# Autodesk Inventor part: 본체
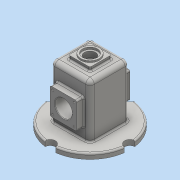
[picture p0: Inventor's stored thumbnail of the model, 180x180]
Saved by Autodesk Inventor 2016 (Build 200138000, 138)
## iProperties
Created: 2018-07
Part Number: 본체
Material: 일반
Document SubType Name: Modeling
Designer: 2-PC02
Density: 1 g/cm^3
Appearance: 기본값
Mass: 461.374 g
Surface Area: 953.172 cm^2
Volume: 461.374 cm^3
Author: 2-PC02
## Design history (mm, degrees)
sketch "스케치1"
  geometry: C1 r 75 at (0, 0); 1 further point
  constraints: 1 centre point, 1 coincident
  dimensions: "d0" = 150 diameter of C1
extrude "돌출1" new body sketch "스케치1" distance "d1" = 10; taper "d2" = 0 deg
sketch "스케치2"
  geometry: L1 (37, -37)-(-37, -37); L2 (-37, -37)-(-37, 37); L3 (-37, 37)-(37, 37); L4 (37, 37)-(37, -37); L5 (37, -37)-(-37, 37); L6 (-37, -37)-(37, 37); 1 further point
  constraints: 12 end point, 2 midpoint, 2 parallel, 1 horizontal, 1 perpendicular
  dimensions: "d3" = 74 distance of L2.end L3.end; "d4" = 74 distance of L1.end L2.end
extrude "돌출2" join sketch "스케치2" distance "d5" = 100; taper "d6" = 0 deg
sketch "스케치3"
  geometry: L1 (20, -20)-(-20, -20); L2 (-20, -20)-(-20, 20); L3 (-20, 20)-(20, 20); L4 (20, 20)-(20, -20); L5 (20, -20)-(-20, 20); L6 (-20, -20)-(20, 20); 1 further point
  constraints: 12 end point, 2 midpoint, 2 parallel, 1 horizontal, 1 perpendicular
  dimensions: "d7" = 40 distance of L2.end L3.end; "d8" = 40 distance of L3.end L1.start
extrude "돌출3" join sketch "스케치3" distance "d9" = 7; taper "d10" = 0 deg
sketch "스케치4"
  geometry: C1 r 17.5 at (0, 0); 1 further point
  constraints: 1 centre point, 1 coincident
  dimensions: "d11" = 35 diameter of C1
extrude "돌출4" join sketch "스케치4" distance "d12" = 3; taper "d13" = 0 deg
sketch "스케치5"
  geometry: L1 (62, 20)-(12, 20); L2 (12, 20)-(12, 70); L3 (12, 70)-(62, 70); L4 (62, 70)-(62, 20); L5 (62, 20)-(12, 70); L6 (12, 20)-(62, 70); L7 (-38, -10)-(112, -10) reference; 2 further points
  constraints: 12 end point, 2 midpoint, 2 parallel, 1 horizontal, 1 perpendicular
  dimensions: "d14" = 50 distance of L2.end L3.end; "d15" = 50 distance of L1.end L2.end; "d16" = 55 distance from line of L7 point (37, 45)
extrude "돌출5" join sketch "스케치5" distance "d17" = 13; taper "d18" = 0 deg
sketch "스케치7"
  geometry: 2 further points
  constraints: 1 coincident
hole "구멍1" sketch "스케치7" at (0, 0) diameter "d23" = 21; stored, may be unused: countersink angle "d27" = 90 deg, drill point angle "d29" = 0 deg; dims "d24" = 6, "d25" = 28, "d26" = 4, "d28" = 15
sketch "스케치12"
  geometry: L1 (-38, -10)-(112, -10) reference; 2 further points
  dimensions: "d54" = 55 distance from line of L1 point (37, 45)
hole "구멍2" sketch "스케치12" at (37, 45) diameter "d55" = 32; stored, may be unused: countersink angle "d59" = 110 deg, drill point angle "d61" = 0 deg; dims "d56" = 6, "d57" = 64, "d58" = 4, "d60" = 100
sketch "스케치13"
  geometry: L1 (10.5, 105)-(-10.5, 105) reference; L2 (-32, 105)-(-32, 80); L3 (-32, 80)-(-25, 77.452); L4 (-32, 105)-(0, 105); L5 (0, 0)-(0, 105); L6 (-37, 10)-(-37, 110) reference; L7 (-50, 39)-(-50, 71) reference; L8 (-25, 77.452)-(0, 77.452)
  constraints: 10 end point, 2 perpendicular, 1 midpoint, 1 point on line
  dimensions: "d62" = 5 distance between parallel lines of L6 L2
revolve "회전3" sketch "스케치13" stored, may be unused: angle "d69" = 90 deg
sketch "스케치14"
  geometry: L1 (-75, 0)-(75, 0) reference; L2 (-32, 0)-(-32, 30); L3 (-32, 30)-(-25, 32.548); L4 (-25, 32.548)-(0, 32.548); L5 (0, 32.548)-(0, 0); L6 (-32, 0)-(0, 0); L7 (-50, 39)-(-50, 71) reference; L8 (-50, 55)-(0, 55)
  constraints: 12 end point, 3 perpendicular, 1 collinear, 1 horizontal, 1 midpoint, 1 point on line
  dimensions: "d70" = 32 distance between parallel lines of L5 L2; "d71" = 110 deg angle of L2 L3; "d72" = 25 distance from line of L2.end L8; "d73" = 7 distance from line of L2 L3.end
revolve "회전4" sketch "스케치14" stored, may be unused: angle "d74" = 90 deg
sketch "스케치15"
  geometry: 2 further points
  constraints: 1 coincident
hole "구멍3" sketch "스케치15" at (0, 0) diameter "d75" = 50; stored, may be unused: countersink angle "d79" = 110 deg, drill point angle "d81" = 0 deg; dims "d76" = 6, "d77" = 64, "d78" = 4, "d80" = 50
fillet "모깎기1" dims "d82" = 8
sketch "스케치17" dims "d55" = 32, "d57" = 64, "d58" = 4, "d60" = 100
  geometry: C1 r 10 at (0, 75); C2 r 10 at (75, 0); C3 r 10 at (0, -75); C4 r 10 at (-75, 0); A1 r 75 centre (0, 0) between (0, 75) and (75, 0) reference; 1 further point
  constraints: 4 centre point, 4 point on circle
  dimensions: "d84" = 20 diameter of C1; "d85" = 20 diameter of C2; "d86" = 20 diameter of C3; "d87" = 20 diameter of C4
extrude "돌출8" cut sketch "스케치17" stored distance "d88" = 25; taper "d89" = 0 deg
sketch "스케치18"
  geometry: L1 (37, 61)-(37, 29) reference; L2 (57, 25)-(17, 65); L3 (17, 25)-(57, 65); 6 further points
  constraints: 4 coincident, 4 end point, 3 midpoint
  dimensions: "d90" = 40 distance of L2.end L3.end; "d91" = 40 distance of L3.start L2.end
hole "구멍4" sketch "스케치18" at (17, 65), (57, 65), (57, 25), (17, 25) diameter "d92" = 3.459; stored, may be unused: countersink angle "d96" = 110 deg, drill point angle "d98" = 118 deg; dims "d93" = 8, "d94" = 64, "d95" = 4, "d97" = 10
fillet "모깎기3" dims "d99" = 8
fillet "모깎기4" dims "d100" = 3
fillet "모깎기5" dims "d101" = 3
fillet "모깎기6" dims "d102" = 3
fillet "모깎기7" dims "d103" = 3
fillet "모깎기8" dims "d104" = 3
fillet "모깎기9" dims "d105" = 3
fillet "모깎기10" dims "d106" = 3
fillet "모깎기11" dims "d107" = 3
fillet "모깎기12" dims "d112" = 3
chamfer "모따기1" distance "d113" = 1; stored, may be unused: second distance "d114" = 2, angle "d115" = 45 deg
node "솔리드1"
mirror "대칭1"
mirror "대칭4"
